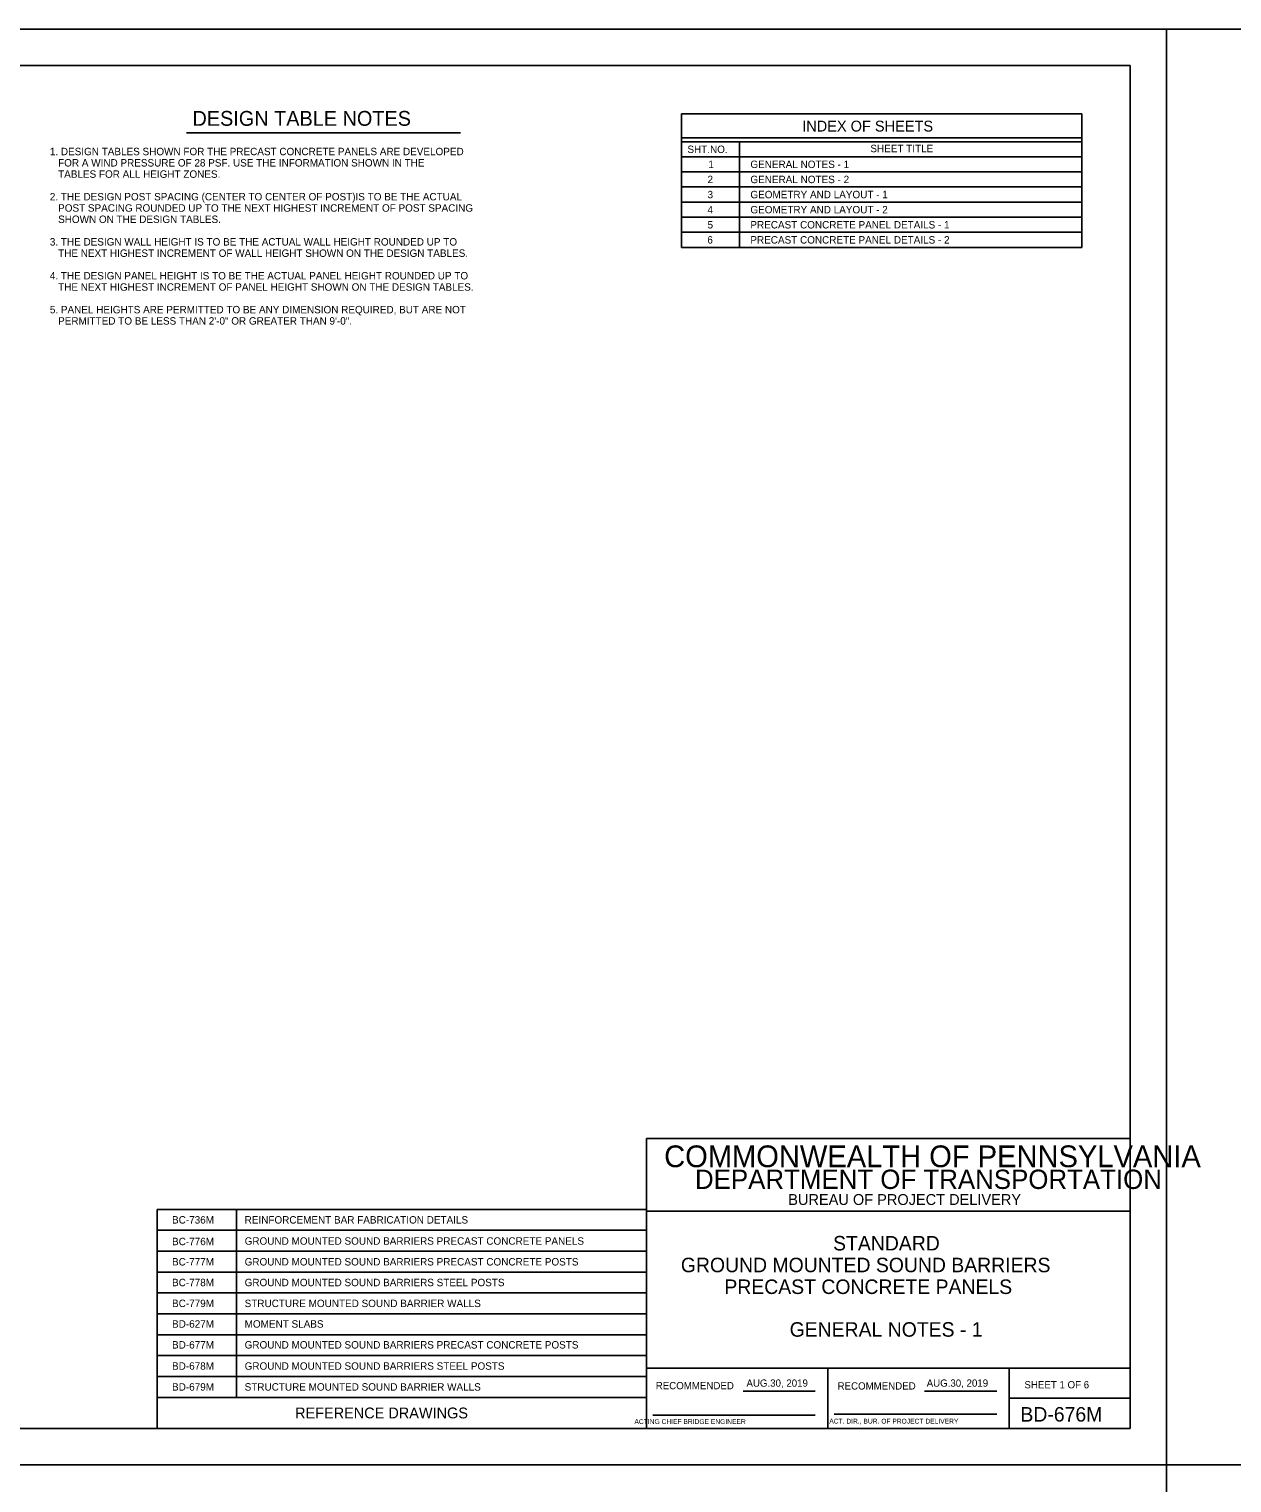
# Model space of a CAD drawing. Extents: x 3761 to 5458, y -616 to 1166.
# Drawn here: x 4132 to 4629, y 564 to 1166 of the extents above; entities that cross this region are included whole.
import ezdxf

# ---------------------------------------------------------------- set-up
doc = ezdxf.new("R2010")
doc.units = 0
for name, color, linetype in [('1', 7, 'Continuous'), ('2', 7, 'Continuous'), ('PLT-BNDY', 7, 'Continuous')]:
    doc.layers.add(name, color=color, linetype=linetype)

msp = doc.modelspace()

# ---------------------------------------------------------------- linework, layer by layer
at = {"layer": '1'}
for p, q in [((4567.34, 1130.69), (4401.77, 1130.69)), ((4401.77, 1075.36), (4401.77, 1130.69)), ((4567.34, 1075.36), (4567.34, 1130.69)), ((4197.06, 1122.78), (4310.37, 1122.78)), ((4567.34, 1120.69), (4401.77, 1120.69)), ((4567.34, 1119.11), (4401.77, 1119.11)), ((4425.81, 1075.36), (4425.81, 1119.11)), ((4567.34, 1112.86), (4401.77, 1112.86)), ((4567.34, 1106.61), (4401.77, 1106.61)), ((4567.34, 1100.36), (4401.77, 1100.36)), ((4567.34, 1094.11), (4401.77, 1094.11)), ((4567.34, 1087.86), (4401.77, 1087.86)), ((4567.34, 1081.61), (4401.77, 1081.61)), ((4567.34, 1075.36), (4401.77, 1075.36)), ((4184.85, 677.35), (4184.85, 586.69)), ((4184.85, 677.35), (4387.34, 677.35)), ((4217.69, 677.35), (4217.69, 599.59)), ((4184.85, 668.71), (4387.34, 668.71)), ((4184.85, 660.07), (4387.34, 660.07)), ((4184.85, 651.43), (4387.34, 651.43)), ((4184.85, 642.79), (4387.34, 642.79)), ((4184.85, 634.15), (4387.34, 634.15)), ((4184.85, 625.51), (4387.34, 625.51)), ((4184.85, 616.87), (4387.34, 616.87)), ((4184.85, 608.23), (4387.34, 608.23)), ((4184.85, 599.59), (4387.34, 599.59))]:
    msp.add_line(p, q, dxfattribs=at)
at = {"layer": '2'}
for p, q in [((3801.34, 1150.69), (4587.34, 1150.69)), ((4587.34, 1150.69), (4587.34, 586.69)), ((4587.34, 706.69), (4387.34, 706.69)), ((4387.34, 706.69), (4387.34, 586.69)), ((4587.34, 586.69), (4587.34, 706.69)), ((4587.34, 676.69), (4387.34, 676.69)), ((4587.34, 611.69), (4387.34, 611.69)), ((4462.34, 586.69), (4462.34, 611.69)), ((4537.34, 611.69), (4537.34, 586.69)), ((4427.31, 602.19), (4457.07, 602.19)), ((4502.31, 602.19), (4532.21, 602.19)), ((4537.34, 599.19), (4587.34, 599.19)), ((4389.84, 592.19), (4457.07, 592.19)), ((4464.97, 592.57), (4532.21, 592.57)), ((4587.34, 586.69), (3801.34, 586.69)), ((4387.34, 586.69), (4587.34, 586.69))]:
    msp.add_line(p, q, dxfattribs=at)
at = {"layer": 'PLT-BNDY'}
for points in [[(3761.34, 1165.69), (4602.34, 1165.69), (4602.34, 571.69), (3761.34, 571.69)], [(4602.34, 1165.69), (5443.34, 1165.69), (5443.34, 571.69), (4602.34, 571.69)], [(3761.34, 571.69), (4602.34, 571.69), (4602.34, -22.31), (3761.34, -22.31)], [(4602.34, 571.69), (5443.34, 571.69), (5443.34, -22.31), (4602.34, -22.31)]]:
    msp.add_lwpolyline(points, close=True, dxfattribs=at)

# ---------------------------------------------------------------- texts
at = {"layer": '1'}
for s, height, p in [('DESIGN TABLE NOTES', 6.144, (4199.47, 1125.67)), ('INDEX OF SHEETS', 4.5, (4451.68, 1123.3)), ('1. DESIGN TABLES SHOWN FOR THE PRECAST CONCRETE PANELS ARE DEVELOPED', 3.072, (4140.47, 1113.5)), ('SHT.NO.', 3.072, (4404.21, 1114.42)), ('SHEET TITLE', 3.072, (4479.89, 1114.75)), ('   TABLES FOR ALL HEIGHT ZONES.', 3.072, (4140.47, 1104.16)), ('   FOR A WIND PRESSURE OF 28 PSF. USE THE INFORMATION SHOWN IN THE ', 3.072, (4140.47, 1108.83)), ('1', 3.07, (4412.89, 1108.2)), ('GENERAL NOTES - 1', 3.072, (4430.26, 1108.2)), ('2', 3.07, (4412.54, 1101.95)), ('GENERAL NOTES - 2', 3.072, (4430.26, 1101.95)), ('2. THE DESIGN POST SPACING (CENTER TO CENTER OF POST)IS TO BE THE ACTUAL ', 3.072, (4140.47, 1094.81)), ('3', 3.07, (4412.54, 1095.7)), ('GEOMETRY AND LAYOUT - 1', 3.072, (4430.26, 1095.7)), ('   POST SPACING ROUNDED UP TO THE NEXT HIGHEST INCREMENT OF POST SPACING ', 3.072, (4140.47, 1090.14)), ('4', 3.07, (4412.54, 1089.45)), ('GEOMETRY AND LAYOUT - 2', 3.072, (4430.26, 1089.45)), ('   SHOWN ON THE DESIGN TABLES.', 3.072, (4140.47, 1085.47)), ('5', 3.07, (4412.54, 1083.2)), ('PRECAST CONCRETE PANEL DETAILS - 1', 3.072, (4430.26, 1083.2)), ('3. THE DESIGN WALL HEIGHT IS TO BE THE ACTUAL WALL HEIGHT ROUNDED UP TO', 3.072, (4140.47, 1076.13)), ('6', 3.07, (4412.45, 1076.95)), ('PRECAST CONCRETE PANEL DETAILS - 2', 3.072, (4430.26, 1076.95)), ('   THE NEXT HIGHEST INCREMENT OF WALL HEIGHT SHOWN ON THE DESIGN TABLES.', 3.072, (4140.47, 1071.45)), ('4. THE DESIGN PANEL HEIGHT IS TO BE THE ACTUAL PANEL HEIGHT ROUNDED UP TO', 3.072, (4140.47, 1062.11)), ('   THE NEXT HIGHEST INCREMENT OF PANEL HEIGHT SHOWN ON THE DESIGN TABLES.', 3.072, (4140.47, 1057.44)), ('5. PANEL HEIGHTS ARE PERMITTED TO BE ANY DIMENSION REQUIRED, BUT ARE NOT', 3.072, (4140.47, 1048.09)), ('   PERMITTED TO BE LESS THAN 2\'-0" OR GREATER THAN 9\'-0".', 3.072, (4140.47, 1043.42)), ('BC-736M', 3.072, (4191.03, 671.5)), ('REINFORCEMENT BAR FABRICATION DETAILS', 3.072, (4221.06, 671.5)), ('BC-776M', 3.072, (4191.03, 662.55)), ('GROUND MOUNTED SOUND BARRIERS PRECAST CONCRETE PANELS', 3.072, (4221.06, 662.74)), ('STANDARD', 6, (4464.48, 660.36)), ('BC-777M', 3.072, (4191.03, 654.15)), ('GROUND MOUNTED SOUND BARRIERS PRECAST CONCRETE POSTS', 3.072, (4221.06, 654.15)), ('GROUND MOUNTED SOUND BARRIERS', 6, (4401.5, 651.36)), ('BC-778M', 3.072, (4191.03, 645.58)), ('GROUND MOUNTED SOUND BARRIERS STEEL POSTS', 3.072, (4221.06, 645.58)), ('PRECAST CONCRETE PANELS', 6, (4419.5, 642.36)), ('BC-779M', 3.072, (4191.03, 636.94)), ('STRUCTURE MOUNTED SOUND BARRIER WALLS', 3.072, (4221.06, 636.94)), ('BD-627M', 3.072, (4191.03, 628.42)), ('MOMENT SLABS', 3.072, (4221.06, 628.43)), ('GENERAL NOTES - 1', 6, (4446.5, 624.69)), ('BD-677M', 3.072, (4191.03, 619.78)), ('GROUND MOUNTED SOUND BARRIERS PRECAST CONCRETE POSTS', 3.072, (4221.06, 619.79)), ('BD-678M', 3.072, (4191.03, 611.02)), ('GROUND MOUNTED SOUND BARRIERS STEEL POSTS', 3.072, (4221.06, 611.02)), ('BD-679M', 3.072, (4191.03, 602.38)), ('STRUCTURE MOUNTED SOUND BARRIER WALLS', 3.072, (4221.06, 602.38)), ('SHEET 1 OF 6', 3, (4543.63, 603.32)), ('BD-676M', 6, (4541.97, 589.57)), ('REFERENCE DRAWINGS', 4.4774, (4241.91, 590.9))]:
    msp.add_text(s, height=height, dxfattribs=at).set_placement(p)
at = {"layer": '2'}
for s, height, p in [('COMMONWEALTH OF PENNSYLVANIA', 9, (4394.59, 694.82)), ('DEPARTMENT OF TRANSPORTATION', 8.0002, (4407.34, 685.82)), ('BUREAU OF PROJECT DELIVERY', 4.5, (4445.93, 679.19)), ('AUG.30, 2019', 3, (4428.64, 604)), ('AUG.30, 2019', 3, (4503.19, 604)), ('       ACTING CHIEF BRIDGE ENGINEER', 2.0002, (4376.93, 588.57)), ('  ACT. DIR., BUR. OF PROJECT DELIVERY', 2.0002, (4461.37, 588.75))]:
    msp.add_text(s, height=height, dxfattribs=at).set_placement(p)
for p in [(4391.11, 602.94), (4466.33, 602.82)]:
    msp.add_text('RECOMMENDED', height=3, rotation=360, dxfattribs=at).set_placement(p)

doc.saveas('drawing.dxf')
